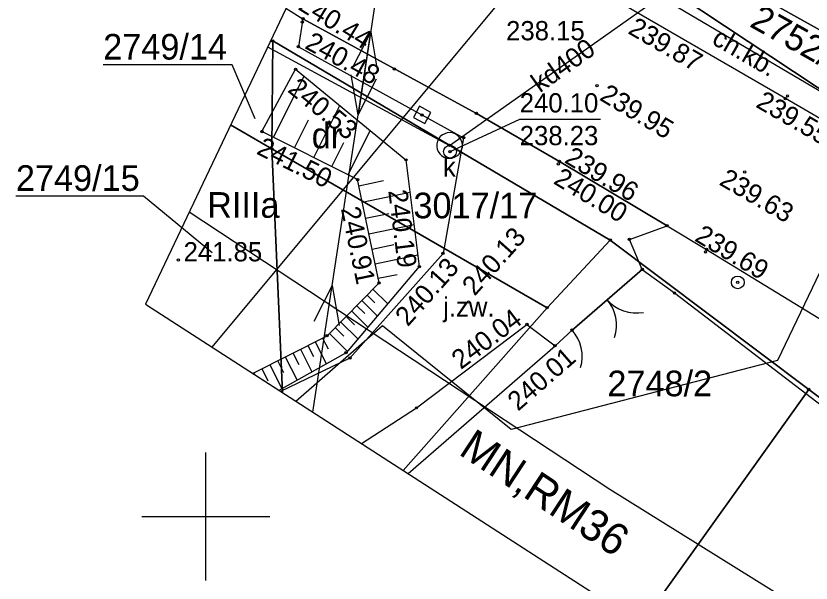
# Model space of a CAD drawing. Extents: x 6596400 to 6597200, y 5539751 to 5540251.
# Drawn here: x 6596642.58 to 6596673.62, y 5540098.41 to 5540120.52 of the extents above; entities that cross this region are included whole.
import ezdxf

# ---------------------------------------------------------------- set-up
doc = ezdxf.new("R2010")
doc.units = 0
for name, color, linetype in [('000 Inne (niezydentyfikowane)', 7, 'Continuous'), ('140-Punkty robocze', 7, 'Continuous'), ('203-punkt graniczny', 7, 'Continuous'), ('209-oznaczenie konturu klasyfikacyjnego', 7, 'Continuous'), ('210-oznaczenie konturu użytku gruntowego', 7, 'Continuous'), ('211-numer działki ewidencyjnej', 7, 'Continuous'), ('217-kontur klasyfikacyjny', 7, 'Continuous'), ('218-kontur użytku gruntowego', 7, 'Continuous'), ('219-działka ewidencyjna', 7, 'Continuous'), ('brama', 7, 'Continuous'), ('chodnik', 7, 'Continuous'), ('chodnik-Atr17', 7, 'Continuous'), ('furtka', 7, 'Continuous'), ('jezdnia', 7, 'Continuous'), ('jezdnia-Atr17', 7, 'Continuous'), ('komora podziemna', 7, 'Continuous'), ('krawężnik', 7, 'Continuous'), ('Linia obszaru zagospodarowania terenu', 7, 'Continuous'), ('ogrodzenie trwałe', 7, 'Continuous'), ('Opis obszaru zagospodarowania terenu', 7, 'Continuous'), ('pikieta sztuczna', 7, 'Continuous'), ('pikieta sztuczna-Atr2', 7, 'Continuous'), ('przewód elektroenergetyczny niskiego napięcia', 7, 'Continuous'), ('przewód elektroenergetyczny podziemny', 7, 'Continuous'), ('przewód kanalizacyjny', 7, 'Continuous'), ('przewód kanalizacyjny-Atr1', 7, 'Continuous'), ('przewód wodociągowy', 7, 'Continuous'), ('rzedna', 7, 'Continuous'), ('rzedna-Atr2', 7, 'Continuous'), ('rzedna-Atr3', 7, 'Continuous'), ('skarpa nieumocniona', 7, 'Continuous'), ('Wstawianie ramki sekcyjnej z opisem', 7, 'Continuous'), ('właz do komory lub kanału - kwadratowy', 7, 'Continuous'), ('właz do komory lub kanału - okrągły', 7, 'Continuous'), ('właz do komory lub kanału - okrągły-Atr17', 7, 'Continuous'), ('Zakres', 7, 'Continuous')]:
    doc.layers.add(name, color=color, linetype=linetype)

# ---------------------------------------------------------------- blocks, each defined once
blk = doc.blocks.new('203')
blk.add_circle((0, 0), 0.045)
blk = doc.blocks.new('SUEP1')
for p, q in [((5, 0), (3.5, 0.5)), ((15, 0), (13.5, 0.5)), ((0, 0), (5, 0)), ((5, 0), (3.5, -0.5)), ((5, 0), (15, 0)), ((15, 0), (13.5, -0.5))]:
    blk.add_line(p, q)
blk = doc.blocks.new('OK02')
for centre, start, end in [((-1.5, 0), 0, 60), ((1.5, 0), 120, 180)]:
    blk.add_arc(centre, 1.5, start, end)
blk = doc.blocks.new('OK04')
blk.add_arc((1.5, 0.001), 1.5, 120, 180)
blk = doc.blocks.new('US22')
blk.add_circle((0, 0), 0.25)
blk = doc.blocks.new('PW01')
blk.add_circle((0, 0), 0.045)
blk = doc.blocks.new('US22A')
blk.add_lwpolyline([(-0.25, -0.25), (0.25, -0.25), (0.25, 0.25), (-0.25, 0.25)], close=True)
blk = doc.blocks.new('RAMKA500K')
for p, q in [((250, 98.5), (250, 103.5)), ((247.5, 101), (252.5, 101))]:
    blk.add_line(p, q)
blk = doc.blocks.new('PIKIETA')
blk.add_circle((0, 0), 0.045)

msp = doc.modelspace()

# ---------------------------------------------------------------- linework, layer by layer
at = {"layer": '000 Inne (niezydentyfikowane)'}
for p, q in [((6596652.64, 5540115.79), (6596653.83, 5540118.17)), ((6596654.21, 5540115), (6596655.23, 5540117.03)), ((6596653.46, 5540115.38), (6596654.01, 5540116.47)), ((6596655.55, 5540114.33), (6596656.41, 5540116.05)), ((6596654.91, 5540114.65), (6596655.38, 5540115.58)), ((6596655.97, 5540113.9), (6596656.93, 5540114.1)), ((6596656.1, 5540113.26), (6596657.97, 5540113.65)), ((6596656.23, 5540112.63), (6596657.14, 5540112.82)), ((6596656.36, 5540112.02), (6596658.13, 5540112.39)), ((6596656.49, 5540111.43), (6596657.34, 5540111.61)), ((6596656.61, 5540110.85), (6596658.27, 5540111.2)), ((6596656.72, 5540110.29), (6596657.46, 5540110.44)), ((6596656.52, 5540109.87), (6596657.1, 5540109.3)), ((6596656.29, 5540109.63), (6596656.59, 5540109.34)), ((6596655.89, 5540109.22), (6596656.2, 5540108.92)), ((6596656.09, 5540109.43), (6596656.69, 5540108.83)), ((6596655.68, 5540109.02), (6596656.32, 5540108.39)), ((6596655.26, 5540108.59), (6596655.93, 5540107.93)), ((6596655.47, 5540108.8), (6596655.8, 5540108.48)), ((6596655.04, 5540108.37), (6596655.39, 5540108.03)), ((6596654.55, 5540107.96), (6596654.77, 5540107.54)), ((6596654.82, 5540108.14), (6596655.52, 5540107.45)), ((6596653.98, 5540107.67), (6596654.2, 5540107.24)), ((6596654.27, 5540107.82), (6596654.7, 5540106.96)), ((6596653.4, 5540107.38), (6596653.63, 5540106.93)), ((6596653.69, 5540107.53), (6596654.14, 5540106.64)), ((6596652.8, 5540107.08), (6596653.03, 5540106.62)), ((6596653.1, 5540107.23), (6596653.56, 5540106.32)), ((6596652.18, 5540106.77), (6596652.42, 5540106.29)), ((6596652.5, 5540106.92), (6596652.97, 5540105.99)), ((6596651.87, 5540106.61), (6596651.912, 5540106.527))]:
    msp.add_line(p, q, dxfattribs=at)
at = {"layer": '211-numer działki ewidencyjnej'}
for points in [[(6596651.92, 5540116.51), (6596651.02, 5540118.62), (6596645.992, 5540118.62)], [(6596650.24, 5540111.28), (6596647.57, 5540113.5), (6596642.585, 5540113.5)]]:
    msp.add_lwpolyline(points, dxfattribs=at)
at = {"layer": '217-kontur klasyfikacyjny'}
for points in [[(6596652.58, 5540115.34), (6596650.964, 5540116.273)], [(6596652.996, 5540105.829), (6596652.58, 5540115.34)], [(6596673.53, 5540105.96), (6596666.995, 5540096.807)], [(6596682.08, 5540099.52), (6596673.53, 5540105.96)]]:
    msp.add_lwpolyline(points, dxfattribs=at)
at = {"layer": '218-kontur użytku gruntowego'}
for points in [[(6596681.92, 5540115.54), (6596662.85, 5540126.18)], [(6596662.85, 5540126.18), (6596681.92, 5540115.54)], [(6596663.08, 5540124.88), (6596681.02, 5540113.01)], [(6596681.02, 5540113.01), (6596663.08, 5540124.88)], [(6596652.61, 5540119.55), (6596652.54, 5540119.591)], [(6596652.54, 5540119.591), (6596652.61, 5540119.55)], [(6596652.58, 5540115.34), (6596652.61, 5540119.55)], [(6596652.61, 5540119.55), (6596652.58, 5540115.34)], [(6596665.78, 5540111.78), (6596652.61, 5540119.55)], [(6596652.61, 5540119.55), (6596665.78, 5540111.78)], [(6596652.58, 5540115.34), (6596650.964, 5540116.273)], [(6596650.964, 5540116.273), (6596652.58, 5540115.34)], [(6596652.996, 5540105.829), (6596652.58, 5540115.34)], [(6596652.58, 5540115.34), (6596663.32, 5540109.14)], [(6596663.32, 5540109.14), (6596652.58, 5540115.34)], [(6596652.58, 5540115.34), (6596652.996, 5540105.829)], [(6596665.78, 5540111.78), (6596663.32, 5540109.14)], [(6596663.32, 5540109.14), (6596665.78, 5540111.78)], [(6596673.53, 5540105.96), (6596665.78, 5540111.78)], [(6596665.78, 5540111.78), (6596673.53, 5540105.96)], [(6596663.32, 5540109.14), (6596657.703, 5540102.795)], [(6596657.703, 5540102.795), (6596663.32, 5540109.14)], [(6596673.53, 5540105.96), (6596666.995, 5540096.807)], [(6596666.995, 5540096.807), (6596673.53, 5540105.96)], [(6596682.08, 5540099.52), (6596673.53, 5540105.96)], [(6596673.53, 5540105.96), (6596682.08, 5540099.52)]]:
    msp.add_lwpolyline(points, dxfattribs=at)
at = {"layer": '219-działka ewidencyjna'}
for points in [[(6596681.92, 5540115.54), (6596662.85, 5540126.18)], [(6596681.02, 5540113.01), (6596663.08, 5540124.88)], [(6596652.54, 5540119.591), (6596652.61, 5540119.55)], [(6596652.58, 5540115.34), (6596652.61, 5540119.55)], [(6596665.78, 5540111.78), (6596652.61, 5540119.55)], [(6596652.58, 5540115.34), (6596650.964, 5540116.273)], [(6596663.32, 5540109.14), (6596652.58, 5540115.34)], [(6596652.996, 5540105.829), (6596652.58, 5540115.34)], [(6596663.32, 5540109.14), (6596665.78, 5540111.78)], [(6596673.53, 5540105.96), (6596665.78, 5540111.78)], [(6596657.703, 5540102.795), (6596663.32, 5540109.14)], [(6596666.995, 5540096.807), (6596673.53, 5540105.96)], [(6596682.08, 5540099.52), (6596673.53, 5540105.96)]]:
    msp.add_lwpolyline(points, dxfattribs=at)
at = {"layer": 'brama'}
msp.add_lwpolyline([(6596667.03, 5540110.64), (6596664.29, 5540108.27)], dxfattribs=at)
at = {"layer": 'chodnik'}
msp.add_lwpolyline([(6596679.35, 5540113.39), (6596672.62, 5540117.3), (6596666.82, 5540120.65), (6596657.79, 5540125.88), (6596658.68, 5540127.53), (6596667.7, 5540122.3), (6596669.82, 5540121.13), (6596670.99, 5540123.31), (6596672.08, 5540122.71), (6596677.31, 5540119.95)], dxfattribs=at)
at = {"layer": 'furtka'}
msp.add_lwpolyline([(6596664.29, 5540108.27), (6596663.63, 5540107.66)], dxfattribs=at)
at = {"layer": 'jezdnia'}
for points in [[(6596728.26, 5540094.5), (6596723.35, 5540095.14), (6596720.92, 5540095.72), (6596718.03, 5540096.54), (6596712.8, 5540098.2), (6596708.8, 5540099.55), (6596704.7, 5540101.24), (6596694.34, 5540105.7), (6596683.34, 5540111.32), (6596679.35, 5540113.39), (6596672.62, 5540117.3), (6596666.82, 5540120.65), (6596657.79, 5540125.88), (6596655.967, 5540126.802)], [(6596653.124, 5540120.82), (6596653.79, 5540120.41), (6596660.56, 5540116.72), (6596663.8, 5540114.85), (6596668, 5540112.34), (6596669.54, 5540111.42), (6596675.97, 5540107.49), (6596679.93, 5540105.19), (6596682.35, 5540103.89), (6596691.43, 5540099.24), (6596702.2, 5540094.56), (6596706.34, 5540093.02), (6596710.59, 5540091.59), (6596715.92, 5540090.16), (6596720.02, 5540089.23), (6596724.29, 5540088.47), (6596726.93, 5540087.96), (6596734.57, 5540086.51), (6596738.41, 5540085.75), (6596741.83, 5540085.11), (6596743.38, 5540084.84), (6596743.64, 5540085.7), (6596748.72, 5540084.9)], [(6596656.07, 5540103.847), (6596658.22, 5540105.24), (6596662.53, 5540108.49), (6596663.63, 5540107.66), (6596664.29, 5540108.27), (6596667.03, 5540110.64), (6596666.53, 5540111.81), (6596668, 5540112.34), (6596663.8, 5540114.85), (6596660.56, 5540116.72), (6596653.79, 5540120.41), (6596653.61, 5540119.32), (6596660.06, 5540115.77), (6596659.26, 5540111.26), (6596655.62, 5540107.18), (6596652.912, 5540105.883)]]:
    msp.add_lwpolyline(points, dxfattribs=at)
at = {"layer": 'komora podziemna'}
msp.add_lwpolyline([(6596659.13, 5540115.15), (6596659.2, 5540115.08), (6596659.29, 5540115.02), (6596659.39, 5540114.98), (6596659.49, 5540114.97), (6596659.6, 5540114.98), (6596659.7, 5540115.01), (6596659.79, 5540115.06), (6596659.87, 5540115.12), (6596659.93, 5540115.21), (6596659.98, 5540115.3), (6596660.01, 5540115.4), (6596660.01, 5540115.51), (6596659.99, 5540115.61), (6596659.95, 5540115.7), (6596659.89, 5540115.79), (6596659.82, 5540115.86), (6596659.73, 5540115.92), (6596659.63, 5540115.96), (6596659.53, 5540115.97), (6596659.42, 5540115.96), (6596659.32, 5540115.93), (6596659.23, 5540115.88), (6596659.15, 5540115.82), (6596659.09, 5540115.73), (6596659.04, 5540115.64), (6596659.01, 5540115.54), (6596659.01, 5540115.43), (6596659.03, 5540115.33), (6596659.07, 5540115.24)], close=True, dxfattribs=at)
at = {"layer": 'krawężnik'}
for points in [[(6596712.8, 5540098.2), (6596708.8, 5540099.55), (6596704.7, 5540101.24), (6596694.34, 5540105.7), (6596683.34, 5540111.32), (6596679.35, 5540113.39), (6596672.62, 5540117.3), (6596666.82, 5540120.65), (6596657.79, 5540125.88), (6596655.967, 5540126.802)], [(6596653.124, 5540120.82), (6596653.79, 5540120.41), (6596660.56, 5540116.72), (6596663.8, 5540114.85), (6596668, 5540112.34), (6596669.54, 5540111.42), (6596675.97, 5540107.49), (6596679.93, 5540105.19), (6596682.35, 5540103.89), (6596691.43, 5540099.24), (6596702.2, 5540094.56), (6596706.34, 5540093.02), (6596710.59, 5540091.59)]]:
    msp.add_lwpolyline(points, dxfattribs=at)
at = {"layer": 'Linia obszaru zagospodarowania terenu'}
msp.add_lwpolyline([(6596649.353, 5540112.883), (6596665.77, 5540102.07), (6596672.77, 5540097.71), (6596678.05, 5540093.55), (6596689.77, 5540082.95), (6596691.734, 5540080.864)], dxfattribs=at)
at = {"layer": 'ogrodzenie trwałe'}
for points in [[(6596667.03, 5540110.64), (6596668.29, 5540109.72), (6596674.46, 5540105.01), (6596681.86, 5540099.47), (6596691.51, 5540088.79), (6596685.94, 5540084.598)], [(6596657.89, 5540102.675), (6596663.63, 5540107.66)]]:
    msp.add_lwpolyline(points, dxfattribs=at)
at = {"layer": 'przewód elektroenergetyczny podziemny'}
msp.add_lwpolyline([(6596685.598, 5540124.906), (6596682.98, 5540117.67), (6596678.46, 5540119.92), (6596672.31, 5540107.09), (6596661.92, 5540104.4), (6596656.89, 5540108.44), (6596653.516, 5540105.493)], dxfattribs=at)
at = {"layer": 'przewód kanalizacyjny'}
msp.add_lwpolyline([(6596652.409, 5540119.314), (6596659.51, 5540115.47), (6596667.73, 5540121.28), (6596680.3, 5540113.87), (6596707.99, 5540100.58), (6596711.34, 5540100.47), (6596715.95, 5540100.45)], dxfattribs=at)
at = {"layer": 'przewód wodociągowy'}
msp.add_lwpolyline([(6596650.243, 5540107.602), (6596668.68, 5540129.73)], dxfattribs=at)
at = {"layer": 'rzedna-Atr2'}
msp.add_lwpolyline([(6596659.53, 5540115.23), (6596662.25, 5540116.5), (6596665.396, 5540116.5)], dxfattribs=at)
at = {"layer": 'skarpa nieumocniona'}
msp.add_lwpolyline([(6596657.81, 5540114.91), (6596658.33, 5540110.75), (6596655.47, 5540107.39), (6596652.85, 5540105.92), (6596651.82, 5540106.58), (6596654.73, 5540108.05), (6596656.76, 5540110.11), (6596655.92, 5540114.14), (6596652.19, 5540116.01), (6596653.5, 5540118.44)], close=True, dxfattribs=at)
msp.add_lwpolyline([(6596657.81, 5540114.91), (6596658.33, 5540110.75), (6596655.47, 5540107.39), (6596652.85, 5540105.92), (6596651.82, 5540106.58), (6596654.73, 5540108.05), (6596656.76, 5540110.11), (6596655.92, 5540114.14), (6596652.19, 5540116.01), (6596653.5, 5540118.44)], close=True, dxfattribs=at)
at = {"layer": 'Zakres'}
msp.add_lwpolyline([(6596822.22, 5540097.5), (6596800.39, 5540105.4), (6596755.76, 5540121.45), (6596697.73, 5540120.74), (6596659.35, 5540133.92), (6596647.64, 5540109.28), (6596697.73, 5540077), (6596721.01, 5540057.77), (6596727.72, 5540045.95), (6596731.95, 5540033.61), (6596741.17, 5540031.18), (6596755.59, 5540029.2), (6596757.85, 5540044.22), (6596787.25, 5540055.04), (6596806.3, 5540048.33), (6596813.97, 5540042.6), (6596833.15, 5540068.58), (6596822.3, 5540077.75)], close=True, dxfattribs=at)

# ---------------------------------------------------------------- block references
at = {"layer": '140-Punkty robocze'}
for p in [(6596653.77, 5540120.29), (6596657.36, 5540118.45), (6596672.7, 5540117.4), (6596658.44, 5540116.66), (6596660.56, 5540116.72), (6596660.06, 5540115.77), (6596659.51, 5540115.47), (6596659.53, 5540115.23), (6596657.81, 5540114.91), (6596655.92, 5540114.14), (6596668, 5540112.34), (6596666.53, 5540111.81), (6596669.5, 5540111.32), (6596667.03, 5540110.64), (6596670.76, 5540110.13), (6596668.29, 5540109.72), (6596664.29, 5540108.27), (6596654.73, 5540108.05), (6596655.47, 5540107.39), (6596655.62, 5540107.18), (6596658.22, 5540105.24)]:
    msp.add_blockref('PIKIETA', p, dxfattribs=at)
at = {"layer": '203-punkt graniczny'}
for p in [(6596652.61, 5540119.55), (6596652.58, 5540115.34), (6596665.78, 5540111.78), (6596663.32, 5540109.14), (6596673.53, 5540105.96)]:
    msp.add_blockref('203', p, dxfattribs=at)
at = {"layer": 'brama', "rotation": -139.141}
msp.add_blockref('OK02', (6596665.66, 5540109.455), dxfattribs=at)
at = {"layer": 'furtka', "rotation": -137.25500000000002}
msp.add_blockref('OK04', (6596664.29, 5540108.27), dxfattribs=at)
at = {"layer": 'pikieta sztuczna'}
for p in [(6596653.79, 5540120.41), (6596653.61, 5540119.32), (6596653.5, 5540118.44), (6596665.27, 5540117.8), (6596672.62, 5540117.3), (6596652.19, 5540116.01), (6596663.76, 5540114.75), (6596663.8, 5540114.85), (6596671.03, 5540114.44), (6596669.54, 5540111.42), (6596659.26, 5540111.26), (6596648.93, 5540111), (6596658.33, 5540110.75), (6596656.76, 5540110.11), (6596660.25, 5540109.37), (6596662.53, 5540108.49), (6596663.63, 5540107.66)]:
    msp.add_blockref('PW01', p, dxfattribs=at)
at = {"layer": 'przewód elektroenergetyczny niskiego napięcia'}
for p, rotation in [((6596658.197, 5540131.494), -98.649), ((6596680.96, 5540117.14), 146.444), ((6596654.177, 5540105.067), 81.351)]:
    msp.add_blockref('SUEP1', p, dxfattribs=dict(at, rotation=rotation))
at = {"layer": 'rzedna'}
msp.add_blockref('PW01', (6596659.53, 5540115.23), dxfattribs=at)
at = {"layer": 'Wstawianie ramki sekcyjnej z opisem'}
msp.add_blockref('RAMKA500K', (6596400, 5540000), dxfattribs=at)
at = {"layer": 'właz do komory lub kanału - kwadratowy', "rotation": -28.443000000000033}
msp.add_blockref('US22A', (6596658.44, 5540116.66), dxfattribs=at)
at = {"layer": 'właz do komory lub kanału - okrągły'}
for p in [(6596659.53, 5540115.23), (6596670.76, 5540110.13)]:
    msp.add_blockref('US22', p, dxfattribs=at)

# ---------------------------------------------------------------- texts
at = {"layer": '209-oznaczenie konturu klasyfikacyjnego'}
msp.add_text('RIIIa', height=1, dxfattribs=at).set_placement((6596650.05, 5540112.65))
at = {"layer": '210-oznaczenie konturu użytku gruntowego'}
msp.add_text('dr', height=1, dxfattribs=at).set_placement((6596654.13, 5540115.36))
at = {"layer": '211-numer działki ewidencyjnej'}
msp.add_text('2752/5', height=1, rotation=330.841, dxfattribs=at).set_placement((6596671.18, 5540120.13))
for s, p in [('2749/14', (6596645.992, 5540118.82)), ('2749/15', (6596642.585, 5540113.7)), ('3017/17', (6596658.1, 5540112.63)), ('2748/2', (6596665.67, 5540105.69))]:
    msp.add_text(s, height=1, dxfattribs=at).set_placement(p)
at = {"layer": 'chodnik-Atr17'}
msp.add_text('ch.kb.', height=0.75, rotation=329.99, dxfattribs=at).set_placement((6596669.7, 5540119.46))
at = {"layer": 'jezdnia-Atr17'}
msp.add_text('j.zw.', height=0.75, dxfattribs=at).set_placement((6596659.26, 5540108.8))
at = {"layer": 'Opis obszaru zagospodarowania terenu'}
msp.add_text('MN,RM36', height=1.225, rotation=326.629, dxfattribs=at).set_placement((6596659.82, 5540103.45))
at = {"layer": 'pikieta sztuczna-Atr2'}
for s, rotation, p in [('240.01', 332.178, (6596673.13, 5540121.127)), ('240.44', 328.383, (6596653.557, 5540120.801)), ('239.87', 329.99, (6596666.435, 5540119.861)), ('240.48', 331.407, (6596653.821, 5540119.281)), ('240.53', 320.682, (6596653.155, 5540117.59)), ('239.95', 329.137, (6596665.325, 5540117.266)), ('239.55', 329.99, (6596671.425, 5540116.991)), ('241.50', 333.374, (6596651.934, 5540115.16)), ('239.96', 329.137, (6596663.955, 5540114.826)), ('240.00', 329.137, (6596663.525, 5540114.006)), ('239.63', 329.99, (6596669.995, 5540113.961)), ('240.19', 277.125, (6596657.116, 5540113.707)), ('240.91', 281.774, (6596655.266, 5540113.007)), ('239.69', 329.146, (6596669.035, 5540111.776)), ('240.13', 48.262, (6596660.49, 5540109.571)), ('240.13', 48.262, (6596657.88, 5540108.381)), ('240.04', 37.018, (6596659.952, 5540106.711)), ('240.01', 40.973, (6596662.182, 5540105.084))]:
    msp.add_text(s, height=0.75, rotation=rotation, dxfattribs=at).set_placement(p)
msp.add_text('241.85', height=0.75, dxfattribs=at).set_placement((6596649.13, 5540110.95))
at = {"layer": 'przewód kanalizacyjny-Atr1'}
msp.add_text('kd400', height=0.75, rotation=35.253, dxfattribs=at).set_placement((6596663.036, 5540117.504))
at = {"layer": 'rzedna-Atr2'}
msp.add_text('240.10', height=0.75, dxfattribs=at).set_placement((6596662.25, 5540116.758))
at = {"layer": 'rzedna-Atr3'}
for s, p in [('238.15', (6596661.718, 5540119.572)), ('238.23', (6596662.25, 5540115.482))]:
    msp.add_text(s, height=0.75, dxfattribs=at).set_placement(p)
at = {"layer": 'właz do komory lub kanału - okrągły-Atr17'}
msp.add_text('k', height=0.75, dxfattribs=at).set_placement((6596659.25, 5540114.26))

doc.saveas('drawing.dxf')
